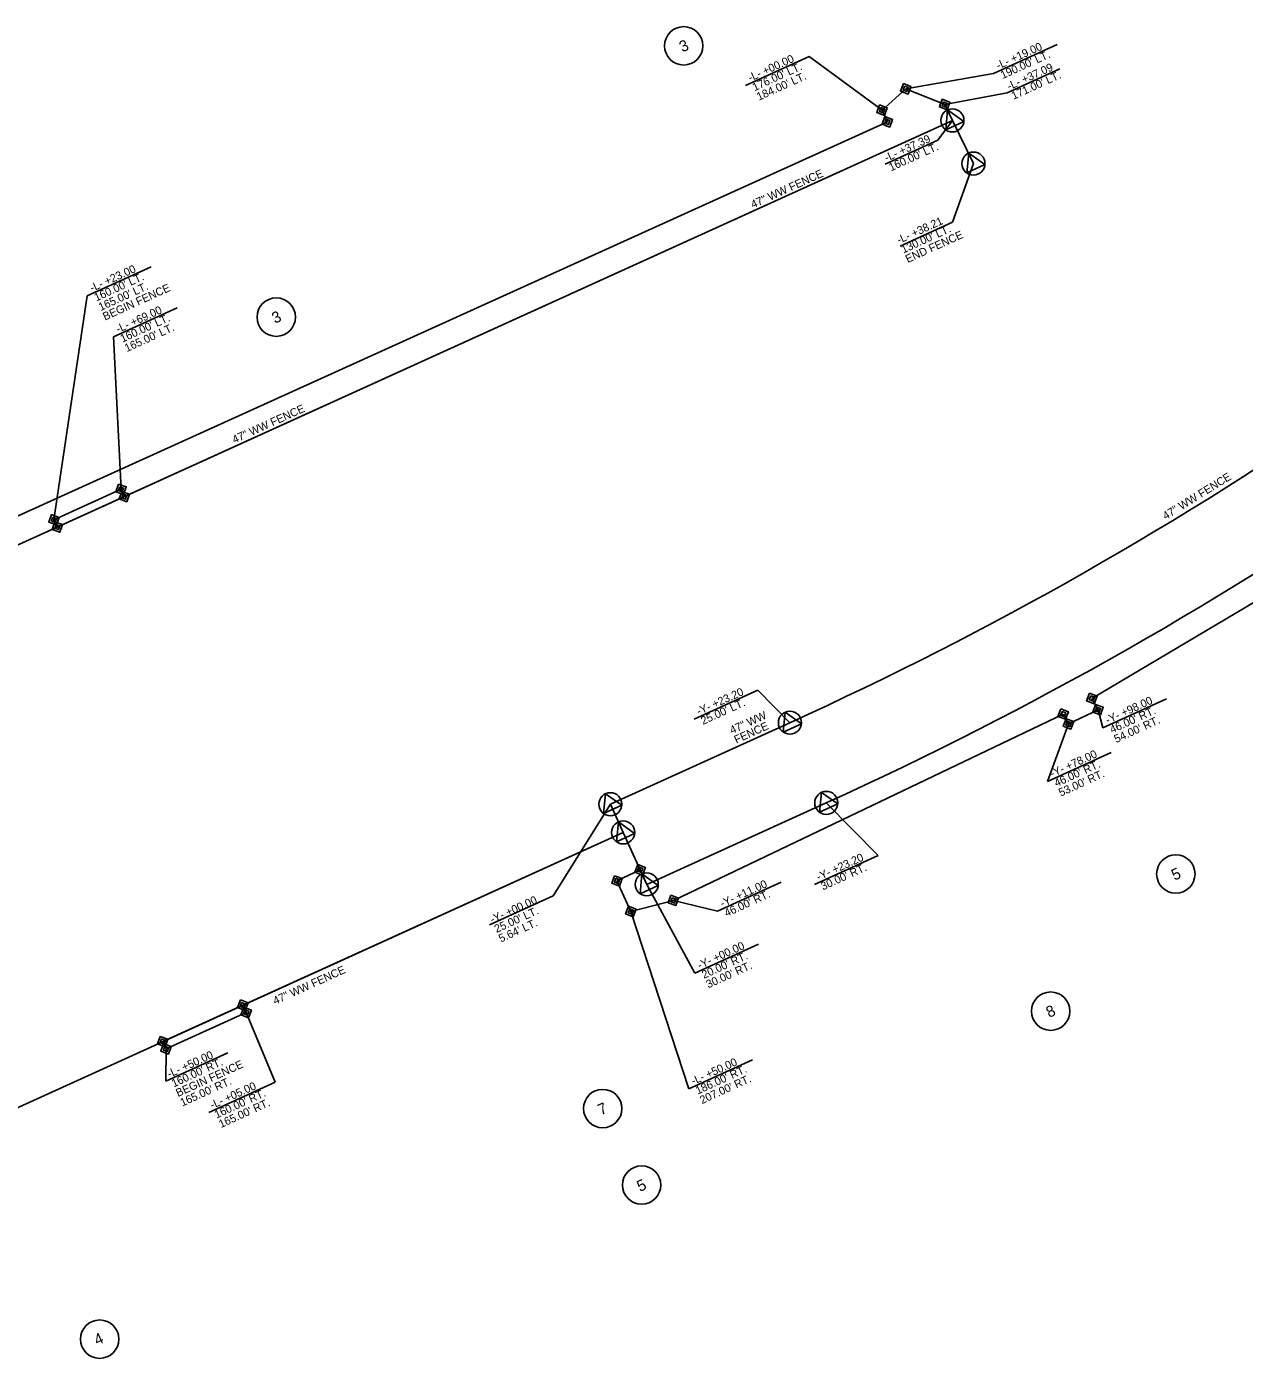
# Model space of a CAD drawing. Extents: x 2242607 to 2250377, y 661355 to 663917.
# Drawn here: x 2249075 to 2249836, y 663085 to 663917 of the extents above; entities that cross this region are included whole.
import ezdxf

# ---------------------------------------------------------------- set-up
doc = ezdxf.new("R2010")
doc.units = 0
for name, color, linetype in [('Prop Easement Permanent Drainage', 7, 'Continuous'), ('Prop Easement Permanent Drainage Station Offsets', 7, 'Continuous'), ('Prop Easement Permanent Drainage Utility', 7, 'Continuous'), ('Prop Easement Permanent Drainage Utility Station Offsets', 7, 'Continuous'), ('Prop Easement Permanent Utility', 7, 'Continuous'), ('Prop Easement Permanent Utility Station Offsets', 7, 'Continuous'), ('Prop Fence Woven Wire', 7, 'Continuous'), ('Prop Parcel Number CELL', 7, 'Continuous'), ('Prop ROW CA Lines', 7, 'Continuous'), ('Prop ROW Marker CELL', 7, 'Continuous'), ('Prop ROW Permanent Easement CELL', 7, 'Continuous'), ('Prop ROW RW CA Lines', 7, 'Continuous'), ('Prop ROW RW Lines', 7, 'Continuous'), ('Prop ROW Station Offsets', 7, 'Continuous')]:
    doc.layers.add(name, color=color, linetype=linetype)

msp = doc.modelspace()

# ---------------------------------------------------------------- linework, layer by layer
at = {"layer": 'Prop Easement Permanent Drainage'}
for p, q in [((2249162.36, 663278.56), (2249212.43, 663301.31)), ((2249212.43, 663301.31), (2249210.36, 663305.86)), ((2249160.29, 663283.11), (2249162.36, 663278.56))]:
    msp.add_line(p, q, dxfattribs=at)
at = {"layer": 'Prop Easement Permanent Drainage Station Offsets'}
for p, q in [((2249212.43, 663301.31), (2249230.66, 663257.79)), ((2249162.36, 663278.56), (2249162.31, 663258.39)), ((2249200.96, 663276.01), (2249162.31, 663258.39)), ((2249230.66, 663257.79), (2249189.09, 663238.85))]:
    msp.add_line(p, q, dxfattribs=at)
at = {"layer": 'Prop Easement Permanent Drainage Utility'}
for p, q in [((2249092.34, 663609.2), (2249134.22, 663628.23)), ((2249134.22, 663628.23), (2249136.29, 663623.68)), ((2249094.4, 663604.65), (2249092.34, 663609.2))]:
    msp.add_line(p, q, dxfattribs=at)
at = {"layer": 'Prop Easement Permanent Drainage Utility Station Offsets'}
for p, q in [((2249113.18, 663749.15), (2249152.98, 663767.29)), ((2249092.34, 663609.2), (2249113.18, 663749.15)), ((2249129.51, 663723.46), (2249169.3, 663741.6)), ((2249134.22, 663628.23), (2249129.51, 663723.46))]:
    msp.add_line(p, q, dxfattribs=at)
at = {"layer": 'Prop Easement Permanent Utility'}
for p, q in [((2249624.64, 663878.46), (2249609.82, 663865.14)), ((2249624.64, 663878.46), (2249648.96, 663868.64)), ((2249609.82, 663865.14), (2249613.13, 663857.86)), ((2249648.96, 663868.64), (2249653.79, 663858.75)), ((2248684.04, 663436.91), (2249613.13, 663857.86)), ((2249740.95, 663497.53), (2249878.58, 663579.34)), ((2249726.34, 663481.62), (2249744.8, 663490.52)), ((2249744.8, 663490.52), (2249740.95, 663497.53)), ((2249479.39, 663371.34), (2249723.03, 663487.79)), ((2249723.03, 663487.79), (2249726.34, 663481.62)), ((2249458.63, 663390.47), (2249444.18, 663383.51)), ((2249444.18, 663383.51), (2249452.87, 663364.39)), ((2249452.87, 663364.39), (2249479.39, 663371.34))]:
    msp.add_line(p, q, dxfattribs=at)
at = {"layer": 'Prop Easement Permanent Utility Station Offsets'}
for p, q in [((2249679.57, 663888.11), (2249719.36, 663906.24)), ((2249524.5, 663880.52), (2249564.29, 663898.66)), ((2249564.29, 663898.66), (2249609.82, 663865.14)), ((2249687.94, 663875.9), (2249720.84, 663890.9)), ((2249679.57, 663888.11), (2249624.64, 663878.46)), ((2249687.94, 663875.9), (2249648.96, 663868.64)), ((2249744.8, 663490.52), (2249747.89, 663479.19)), ((2249747.89, 663479.19), (2249787.68, 663497.33)), ((2249726.34, 663481.62), (2249713.19, 663445.72)), ((2249713.19, 663445.72), (2249752.99, 663463.85)), ((2249507.03, 663364.53), (2249546.82, 663382.66)), ((2249479.39, 663371.34), (2249507.03, 663364.53)), ((2249452.87, 663364.39), (2249488.99, 663253.57)), ((2249488.99, 663253.57), (2249528.79, 663271.71))]:
    msp.add_line(p, q, dxfattribs=at)
at = {"layer": 'Prop Fence Woven Wire'}
for p, q in [((2249094.4, 663604.65), (2249653.79, 663858.75)), ((2249653.79, 663858.75), (2249666.94, 663831.78)), ((2249440.03, 663431.45), (2249552.21, 663482.38)), ((2249448.03, 663413.82), (2249440.03, 663431.45)), ((2249160.29, 663283.11), (2249448.03, 663413.82))]:
    msp.add_line(p, q, dxfattribs=at)
msp.add_arc((2248611.75, 665553.89), 2275, 294.41783, 304.80379, dxfattribs=at)
at = {"layer": 'Prop Parcel Number CELL'}
for p, q in [((2249485.88, 663905.33), (2249485.88, 663905.33)), ((2249231.23, 663735.81), (2249231.23, 663735.81)), ((2249793.42, 663387.86), (2249793.42, 663387.86)), ((2249715.21, 663302.14), (2249715.21, 663302.14)), ((2249435.27, 663241.27), (2249435.27, 663241.27)), ((2249459.56, 663193.49), (2249459.56, 663193.49)), ((2249120.9, 663097.18), (2249120.9, 663097.18))]:
    msp.add_line(p, q, dxfattribs=at)
for centre in [(2249485.88, 663905.33), (2249231.23, 663735.81), (2249793.42, 663387.86), (2249715.21, 663302.14), (2249435.27, 663241.27), (2249459.56, 663193.49), (2249120.9, 663097.18)]:
    msp.add_circle(centre, 12, dxfattribs=at)
at = {"layer": 'Prop ROW CA Lines'}
for q in [(2249552.21, 663482.38), (2249448.03, 663413.82)]:
    msp.add_line((2249440.03, 663431.45), q, dxfattribs=at)
msp.add_arc((2248611.75, 665553.89), 2275, 294.41783, 304.80379, dxfattribs=at)
at = {"layer": 'Prop ROW Marker CELL'}
for p, q in [((2249624.64, 663878.46), (2249624.64, 663878.46)), ((2249609.82, 663865.14), (2249609.82, 663865.14)), ((2249648.96, 663868.64), (2249648.96, 663868.64)), ((2249613.13, 663857.86), (2249613.13, 663857.86)), ((2249653.79, 663858.75), (2249653.79, 663858.75)), ((2249666.94, 663831.78), (2249666.94, 663831.78)), ((2249134.22, 663628.23), (2249134.22, 663628.23)), ((2249136.29, 663623.68), (2249136.29, 663623.68)), ((2249092.34, 663609.2), (2249092.34, 663609.2)), ((2249094.4, 663604.65), (2249094.4, 663604.65)), ((2249740.95, 663497.53), (2249740.95, 663497.53)), ((2249744.8, 663490.52), (2249744.8, 663490.52)), ((2249552.21, 663482.38), (2249552.21, 663482.38)), ((2249723.03, 663487.79), (2249723.03, 663487.79)), ((2249726.34, 663481.62), (2249726.34, 663481.62)), ((2249574.94, 663432.3), (2249574.94, 663432.3)), ((2249440.03, 663431.45), (2249440.03, 663431.45)), ((2249448.03, 663413.82), (2249448.03, 663413.82)), ((2249458.63, 663390.47), (2249458.63, 663390.47)), ((2249444.18, 663383.51), (2249444.18, 663383.51)), ((2249462.76, 663381.37), (2249462.76, 663381.37)), ((2249479.39, 663371.34), (2249479.39, 663371.34)), ((2249452.87, 663364.39), (2249452.87, 663364.39)), ((2249210.36, 663305.86), (2249210.36, 663305.86)), ((2249212.43, 663301.31), (2249212.43, 663301.31)), ((2249160.29, 663283.11), (2249160.29, 663283.11)), ((2249162.36, 663278.56), (2249162.36, 663278.56))]:
    msp.add_line(p, q, dxfattribs=at)
for points in [[(2249649.59, 663852.89), (2249650.8, 663865.3), (2249660.97, 663858.07)], [(2249662.75, 663825.91), (2249663.96, 663838.33), (2249674.12, 663831.1)], [(2249548.01, 663476.51), (2249549.22, 663488.93), (2249559.39, 663481.69)], [(2249435.83, 663425.58), (2249437.04, 663438), (2249447.21, 663430.76)], [(2249570.75, 663426.43), (2249571.96, 663438.85), (2249582.12, 663431.61)], [(2249443.84, 663407.95), (2249445.04, 663420.37), (2249455.21, 663413.14)], [(2249458.57, 663375.5), (2249459.78, 663387.92), (2249469.94, 663380.68)]]:
    msp.add_lwpolyline(points, close=True, dxfattribs=at)
for centre in [(2249653.79, 663858.75), (2249666.94, 663831.78), (2249552.21, 663482.38), (2249440.03, 663431.45), (2249574.94, 663432.3), (2249448.03, 663413.82), (2249462.76, 663381.37)]:
    msp.add_circle(centre, 7.2, dxfattribs=at)
at = {"layer": 'Prop ROW Permanent Easement CELL'}
for points in [[(2249623.14, 663881.74), (2249627.91, 663879.95), (2249626.13, 663875.19), (2249621.36, 663876.97)], [(2249623.89, 663880.1), (2249626.27, 663879.21), (2249625.38, 663876.82), (2249623, 663877.71)], [(2249608.33, 663868.42), (2249613.09, 663866.63), (2249611.31, 663861.87), (2249606.54, 663863.65)], [(2249609.07, 663866.78), (2249611.46, 663865.89), (2249610.56, 663863.5), (2249608.18, 663864.39)], [(2249647.47, 663871.92), (2249652.24, 663870.14), (2249650.45, 663865.37), (2249645.69, 663867.15)], [(2249648.21, 663870.28), (2249650.6, 663869.39), (2249649.71, 663867.01), (2249647.32, 663867.9)], [(2249611.63, 663861.13), (2249616.4, 663859.35), (2249614.62, 663854.58), (2249609.85, 663856.36)], [(2249612.38, 663859.49), (2249614.76, 663858.6), (2249613.87, 663856.22), (2249611.49, 663857.11)], [(2249132.73, 663631.5), (2249137.49, 663629.72), (2249135.71, 663624.95), (2249130.94, 663626.74)], [(2249133.47, 663629.87), (2249135.86, 663628.98), (2249134.96, 663626.59), (2249132.58, 663627.48)], [(2249134.79, 663626.95), (2249139.56, 663625.17), (2249137.78, 663620.4), (2249133.01, 663622.18)], [(2249135.54, 663625.31), (2249137.92, 663624.42), (2249137.03, 663622.04), (2249134.65, 663622.93)], [(2249090.84, 663612.48), (2249095.61, 663610.7), (2249093.83, 663605.93), (2249089.06, 663607.71)], [(2249091.59, 663610.84), (2249093.97, 663609.95), (2249093.08, 663607.57), (2249090.7, 663608.46)], [(2249092.91, 663607.93), (2249097.68, 663606.14), (2249095.9, 663601.38), (2249091.13, 663603.16)], [(2249093.66, 663606.29), (2249096.04, 663605.4), (2249095.15, 663603.01), (2249092.77, 663603.91)], [(2249739.46, 663500.8), (2249744.23, 663499.02), (2249742.44, 663494.25), (2249737.68, 663496.03)], [(2249740.2, 663499.17), (2249742.59, 663498.27), (2249741.7, 663495.89), (2249739.31, 663496.78)], [(2249721.53, 663491.06), (2249726.3, 663489.28), (2249724.52, 663484.51), (2249719.75, 663486.29)], [(2249743.31, 663493.79), (2249748.08, 663492.01), (2249746.29, 663487.24), (2249741.53, 663489.02)], [(2249744.06, 663492.15), (2249746.44, 663491.26), (2249745.55, 663488.88), (2249743.16, 663489.77)], [(2249722.28, 663489.42), (2249724.67, 663488.53), (2249723.77, 663486.15), (2249721.39, 663487.04)], [(2249724.85, 663484.9), (2249729.62, 663483.11), (2249727.84, 663478.35), (2249723.07, 663480.13)], [(2249725.6, 663483.26), (2249727.98, 663482.37), (2249727.09, 663479.98), (2249724.71, 663480.88)], [(2249457.14, 663393.75), (2249461.91, 663391.96), (2249460.12, 663387.2), (2249455.35, 663388.98)], [(2249457.88, 663392.11), (2249460.27, 663391.22), (2249459.38, 663388.83), (2249456.99, 663389.73)], [(2249442.69, 663386.79), (2249447.46, 663385.01), (2249445.67, 663380.24), (2249440.9, 663382.02)], [(2249443.43, 663385.15), (2249445.82, 663384.26), (2249444.93, 663381.88), (2249442.54, 663382.77)], [(2249477.9, 663374.62), (2249482.67, 663372.84), (2249480.89, 663368.07), (2249476.12, 663369.85)], [(2249451.37, 663367.67), (2249456.14, 663365.89), (2249454.36, 663361.12), (2249449.59, 663362.9)], [(2249452.12, 663366.03), (2249454.5, 663365.14), (2249453.61, 663362.76), (2249451.23, 663363.65)], [(2249478.65, 663372.98), (2249481.03, 663372.09), (2249480.14, 663369.71), (2249477.76, 663370.6)], [(2249208.87, 663309.13), (2249213.64, 663307.35), (2249211.86, 663302.58), (2249207.09, 663304.37)], [(2249209.62, 663307.5), (2249212, 663306.6), (2249211.11, 663304.22), (2249208.73, 663305.11)], [(2249210.94, 663304.58), (2249215.71, 663302.8), (2249213.92, 663298.03), (2249209.16, 663299.81)], [(2249211.68, 663302.94), (2249214.07, 663302.05), (2249213.18, 663299.67), (2249210.79, 663300.56)], [(2249158.79, 663286.39), (2249163.56, 663284.6), (2249161.78, 663279.84), (2249157.01, 663281.62)], [(2249159.54, 663284.75), (2249161.93, 663283.86), (2249161.03, 663281.47), (2249158.65, 663282.36)], [(2249160.86, 663281.83), (2249165.63, 663280.05), (2249163.85, 663275.28), (2249159.08, 663277.07)], [(2249161.61, 663280.2), (2249163.99, 663279.31), (2249163.1, 663276.92), (2249160.72, 663277.81)]]:
    msp.add_lwpolyline(points, close=True, dxfattribs=at)
at = {"layer": 'Prop ROW RW CA Lines'}
for p, q in [((2248636.44, 663396.62), (2249653.79, 663858.75)), ((2249653.79, 663858.75), (2249666.94, 663831.78)), ((2248946.33, 663185.92), (2249448.03, 663413.82))]:
    msp.add_line(p, q, dxfattribs=at)
at = {"layer": 'Prop ROW RW Lines'}
for p, q in [((2249462.76, 663381.37), (2249574.94, 663432.3)), ((2249448.03, 663413.82), (2249462.76, 663381.37))]:
    msp.add_line(p, q, dxfattribs=at)
msp.add_arc((2248611.75, 665553.89), 2330, 294.41783, 304.80379, dxfattribs=at)
at = {"layer": 'Prop ROW Station Offsets'}
for p, q in [((2249644.6, 663846.33), (2249653.79, 663858.75)), ((2249611.73, 663831.36), (2249644.6, 663846.33)), ((2249653.93, 663795.07), (2249666.94, 663831.78)), ((2249621.06, 663780.09), (2249653.93, 663795.07)), ((2249492.32, 663484.57), (2249532.12, 663502.7)), ((2249532.12, 663502.7), (2249552.21, 663482.38)), ((2249574.94, 663432.3), (2249607.33, 663399.4)), ((2249404.24, 663374.19), (2249440.03, 663431.45)), ((2249567.53, 663381.26), (2249607.33, 663399.4)), ((2249364.45, 663356.05), (2249404.24, 663374.19)), ((2249492.9, 663325.88), (2249462.76, 663381.37)), ((2249492.9, 663325.88), (2249532.69, 663344.02))]:
    msp.add_line(p, q, dxfattribs=at)

# ---------------------------------------------------------------- texts
at = {"layer": 'Prop Easement Permanent Drainage Station Offsets'}
for s, p in [('-L- +50.00', (2249164.44, 663260.4)), ("160.00' RT.", (2249167.15, 663254.43)), ('BEGIN FENCE', (2249169.86, 663248.46)), ("165.00' RT.", (2249172.58, 663242.5)), ('-L- +05.00', (2249191.25, 663240.97)), ("160.00' RT.", (2249193.96, 663235)), ("165.00' RT.", (2249196.67, 663229.03))]:
    msp.add_text(s, height=5, rotation=24.43013, dxfattribs=at).set_placement(p)
at = {"layer": 'Prop Easement Permanent Drainage Utility Station Offsets'}
for s, p in [('-L- +23.00', (2249116.1, 663751.53)), ("160.00' LT.", (2249118.81, 663745.56)), ("165.00' LT.", (2249121.52, 663739.6)), ('BEGIN FENCE', (2249124.23, 663733.63)), ('-L- +69.00', (2249132.42, 663725.84)), ("160.00' LT.", (2249135.14, 663719.88)), ("165.00' LT.", (2249137.85, 663713.91))]:
    msp.add_text(s, height=5, rotation=24.43013, dxfattribs=at).set_placement(p)
at = {"layer": 'Prop Easement Permanent Utility Station Offsets'}
for s, p in [('-L- +19.00', (2249682.49, 663890.49)), ('-L- +00.00', (2249527.42, 663882.9)), ("190.00' LT.", (2249685.2, 663884.52)), ("176.00' LT.", (2249530.13, 663876.94)), ('-L- +37.09', (2249689.29, 663877.57)), ("184.00' LT.", (2249532.84, 663870.97)), ("171.00' LT.", (2249692, 663871.6)), ('-Y- +98.00', (2249750.8, 663481.57)), ("46.00' RT.", (2249753.52, 663475.6)), ("54.00' RT.", (2249756.23, 663469.64)), ('-Y- +78.00', (2249716.11, 663448.1)), ("46.00' RT.", (2249718.82, 663442.13)), ("53.00' RT.", (2249721.53, 663436.16)), ('-Y- +11.00', (2249509.95, 663366.91)), ("46.00' RT.", (2249512.66, 663360.94)), ('-L- +50.00', (2249491.91, 663255.95)), ("186.00' RT.", (2249494.62, 663249.98)), ("207.00' RT.", (2249497.33, 663244.02))]:
    msp.add_text(s, height=5, rotation=24.43013, dxfattribs=at).set_placement(p)
at = {"layer": 'Prop Fence Woven Wire'}
for s, rotation, p in [('47" WW FENCE', 24.43013, (2249529.18, 663803.67)), ('47" WW FENCE', 24.43013, (2249205.1, 663656.74)), ('47" WW FENCE', 31.83564, (2249787.06, 663609.01)), ('47" WW', 24.43013, (2249516.04, 663475.19)), ('FENCE', 24.43013, (2249518.75, 663469.23)), ('47" WW FENCE', 24.43013, (2249230.57, 663306.07))]:
    msp.add_text(s, height=5, rotation=rotation, dxfattribs=at).set_placement(p)
at = {"layer": 'Prop Parcel Number CELL'}
for s, p in [('3', (2249485.05, 663901.11)), ('3', (2249230.41, 663731.59)), ('5', (2249792.58, 663383.63)), ('8', (2249714.25, 663297.86)), ('7', (2249434.16, 663236.92)), ('5', (2249458.53, 663189.1)), ('4', (2249119.31, 663093.11))]:
    msp.add_text(s, height=7, rotation=24.49794, dxfattribs=at).set_placement(p)
at = {"layer": 'Prop ROW Station Offsets'}
for s, p in [('-L- +37.39', (2249612.7, 663832.85)), ("160.00' LT.", (2249615.41, 663826.88)), ('-L- +38.21', (2249620.42, 663781.5)), ("130.00' LT.", (2249623.13, 663775.54)), ('END FENCE', (2249625.84, 663769.57)), ('-Y- +23.20', (2249495.24, 663486.95)), ("25.00' LT.", (2249497.95, 663480.98)), ('-Y- +23.20', (2249570.19, 663383.52)), ("30.00' RT.", (2249572.9, 663377.56)), ('-Y- +00.00', (2249366.18, 663356.91)), ("25.00' LT.", (2249368.89, 663350.95)), ("5.64' LT.", (2249371.6, 663344.98)), ('-Y- +00.00', (2249495.82, 663328.26)), ("20.00' RT.", (2249498.53, 663322.3)), ("30.00' RT.", (2249501.24, 663316.33))]:
    msp.add_text(s, height=5, rotation=24.43013, dxfattribs=at).set_placement(p)

doc.saveas('drawing.dxf')
